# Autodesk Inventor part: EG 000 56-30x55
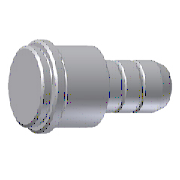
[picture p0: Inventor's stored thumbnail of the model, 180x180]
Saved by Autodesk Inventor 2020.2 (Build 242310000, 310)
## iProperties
Manager: www.cadconsulting.pl
Company: Fabian Stasiak CAD Consulting
IsCustomPart: 0
Created: 2014-02
Part Number: EG 000 56-30x55
Material: DIN 1.7131
Description: Leader Pins
Document SubType Name: Modeling
Designer: F.Stasiak
Standard Revision: 1
Manufacturer: DME
Language: pl-PL
Size Designation: 56-30x55
Categories: <MemberInstance><Categories><Category DisplayName="Forma wtryskowa" InternalName="349578f2-f4d4-4954-8c09-8e99297a61c0" Mnemonic="MOLD"><Category DisplayName="K
Mass: 4.19143 g
Surface Area: 17.8137 cm^2
Volume: 4.19143 cm^3
Density: 7.85 g/cm^3
Appearance: Stal
Catalog Web Link: www.expertbooks.pl
Author: F.Stasiak
Subject: Zbiór ćwiczeń. Autodesk Inventor 2020. Kurs Professional
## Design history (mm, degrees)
sketch "Sketch1"
  geometry: L1 (0, -42.393)-(0, 14.066) reference; L2 (0, 15)-(21, 15); L3 (21, 15)-(21, 7); L4 (20.5, 6)-(23.5, 6); L5 (23.5, 6)-(23.5, 0); L6 (23.5, 0)-(20.5, 0); L7 (21, -1)-(21, -48); L8 (21, -48)-(21, -48); L9 (21, -48)-(21, -50); L10 (21, -50)-(15, -50); L11 (15, -98)-(13.522, -103.518); L12 (11.59, -105)-(0, -105); L13 (15, -50)-(15, -98); L14 (20.5, 0)-(20.5, -1); L15 (20.5, -1)-(21, -1); L16 (20.5, 7)-(21, 7); L17 (20.5, 7)-(20.5, 6); L18 (0, 15)-(0, -105); A1 r 2 centre (11.59, -103) between (11.59, -105) and (13.522, -103.518); 1 further point
  constraints: 38 end point, 7 perpendicular, 6 parallel, 2 collinear, 2 point on circle, 2 point on line, 2 tangent, 2 vertical alignment, 1 centre point, 1 horizontal alignment
  dimensions: "d73" = 6 distance between parallel lines of L6 L4 (derived); "d74" = 9 distance between parallel lines of L2 L4 (derived); "d75" = 56 distance between parallel lines of L10 L4 (derived); "d76" = 2 distance between parallel lines of L10 L8; "d77" = 47 diameter of L5 L1 (derived); "d78" = 55 distance between parallel lines of L12 L10 (derived); "d79" = 42 diameter of L3 L1 (derived); "d89" = 7 distance from line of L12 L11.start (derived); "d92" = 30 diameter of L13 L1 (derived); "d94" = 42 diameter of L7 L1 (derived); "d97" = 2 radius of A1; "d110" = 0.5 distance between parallel lines of L7 L14; "d111" = 1 distance from line of L6.end L15; "d112" = 0.5 distance between parallel lines of L3 L17; "d113" = 1 distance between parallel lines of L4 L16; "d114" = 42 diameter of L9 L18 (derived); "d120" = 15 deg angle of L13 L11
revolve "Revolution1" sketch "Sketch1" stored, may be unused: angle "d100" = 90 deg
chamfer "Chamfer1" distance "d106" = 0.5; stored, may be unused: second distance "d107" = 2, angle "d108" = 45 deg
fillet "Fillet1" dims "d109" = 0.3
sketch "Sketch2"
  geometry: L1 (-11.59, -105)-(11.59, -105) reference; L2 (0, -40.8)-(0, 6.8) reference; C1 r 1.875 at (15.375, -66); C2 r 1.875 at (15.375, -82); 1 further point
  constraints: 2 centre point, 1 equal radius, 1 vertical alignment
  dimensions: "d121" = 3.75 diameter of C1 (derived); "d122" = 23 distance from line of L1 C2.centre (derived); "d123" = 39 distance from line of L1 C1.centre (derived); "d129" = 30.75 diameter of C1.centre L2 (derived)
revolve "Revolution2" sketch "Sketch2" stored, may be unused: angle "d126" = 90 deg
body "Solid1"
other parameters: "d3" = 47 [user parameter], "d2" = 42 [user parameter], "l2" = 9 [user parameter], "l1" = 6 [user parameter], "A_" = 56 [user parameter], "B" = 55 [user parameter], "d91" = 8, "d101" = 0, "d103" = 0, "ob" = 7 [user parameter], "d2_1" = 42 [user parameter], "d2_2" = 42 [user parameter], "B1" = 23 [user parameter], "G1" = 39 [user parameter], "d128" = 0, "L_" = 111 [user parameter]
